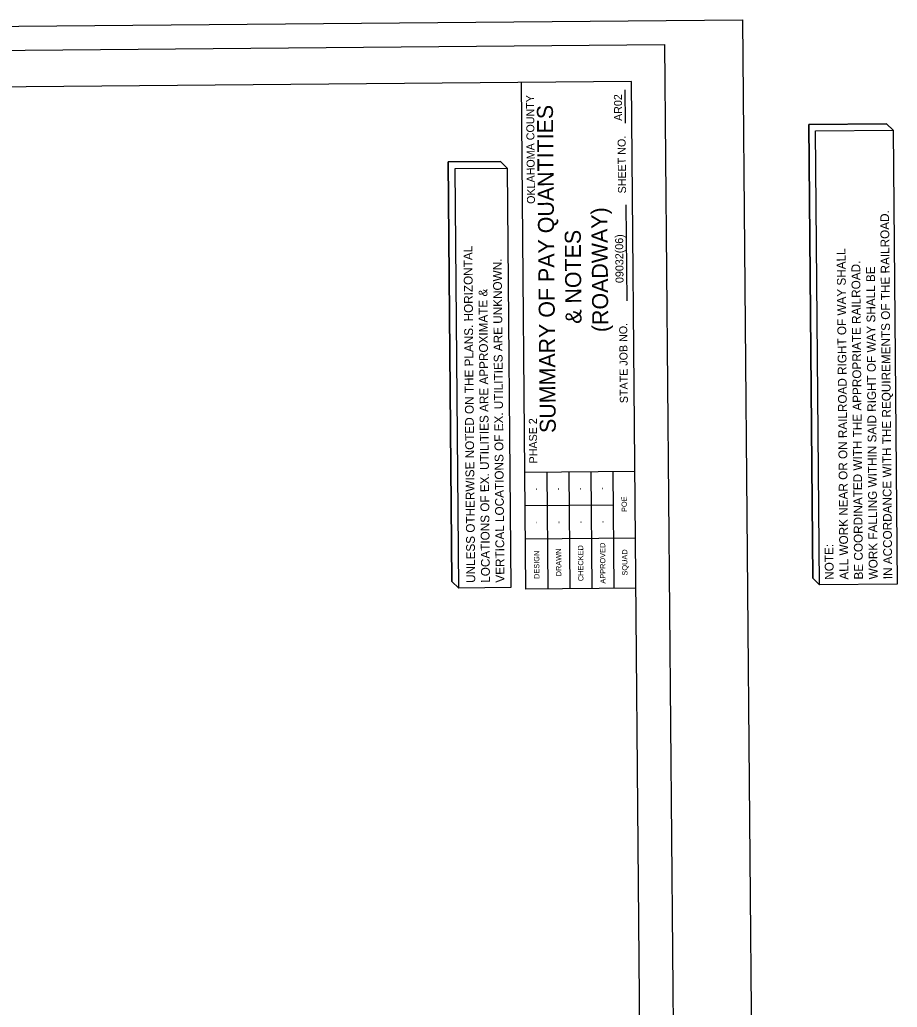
# Model space of a CAD drawing. Extents: x 2151899 to 2151927, y 142567 to 142686.
# Drawn here: x 2151913.59 to 2151926.74, y 142628.6 to 142643.41 of the extents above; entities that cross this region are included whole.
import ezdxf

# ---------------------------------------------------------------- set-up
doc = ezdxf.new("R2010")
doc.units = 0
for name, color, linetype in [('PR_RW_Txt', 7, 'Continuous'), ('PR_Shading_1', 7, 'Continuous'), ('SHT_Plan_Profile_Sheet_Txt', 7, 'Continuous'), ('SHT_Plot_Shape_Full', 7, 'Continuous'), ('SHT_Plot_Shape_Half', 7, 'Continuous'), ('SHT_Sheet_Border', 7, 'Continuous'), ('SHT_Standard_Sheet_Lines', 7, 'Continuous'), ('SHT_Standard_Sheet_Txt', 7, 'Continuous')]:
    doc.layers.add(name, color=color, linetype=linetype)

msp = doc.modelspace()

# ---------------------------------------------------------------- linework, layer by layer
at = {"layer": 'PR_Shading_1'}
for p, q in [((2151926.685, 142641.749), (2151926.584, 142641.848)), ((2151920.897, 142641.182), (2151920.796, 142641.281))]:
    msp.add_line(p, q, dxfattribs=at)
for points in [[(2151926.584, 142641.848), (2151925.419, 142641.838), (2151925.478, 142635.029), (2151925.579, 142634.93)], [(2151925.579, 142634.93), (2151925.52, 142641.739), (2151926.685, 142641.749)], [(2151920.796, 142641.281), (2151920.012, 142641.274), (2151920.067, 142634.982), (2151920.168, 142634.883)], [(2151920.168, 142634.883), (2151920.113, 142641.175), (2151920.897, 142641.182)]]:
    msp.add_lwpolyline(points, dxfattribs=at)
at = {"layer": 'SHT_Plan_Profile_Sheet_Txt'}
for points in [[(2151925.579, 142634.93), (2151925.478, 142635.029), (2151925.419, 142641.838), (2151926.584, 142641.848), (2151926.685, 142641.749)], [(2151920.168, 142634.883), (2151920.067, 142634.982), (2151920.012, 142641.274), (2151920.796, 142641.281), (2151920.897, 142641.182)]]:
    msp.add_lwpolyline(points, dxfattribs=at)
for points in [[(2151925.579, 142634.93), (2151925.52, 142641.739), (2151926.685, 142641.749), (2151926.744, 142634.94)], [(2151920.168, 142634.883), (2151920.113, 142641.175), (2151920.897, 142641.182), (2151920.952, 142634.889)]]:
    msp.add_lwpolyline(points, close=True, dxfattribs=at)
at = {"layer": 'SHT_Plot_Shape_Full'}
msp.add_lwpolyline([(2151900.742, 142607.199), (2151900.427, 142643.197), (2151924.426, 142643.407), (2151924.741, 142607.409)], close=True, dxfattribs=at)
at = {"layer": 'SHT_Plot_Shape_Half'}
msp.add_lwpolyline([(2151901.553, 142608.843), (2151901.255, 142642.842), (2151923.254, 142643.035), (2151923.552, 142609.036)], close=True, dxfattribs=at)
at = {"layer": 'SHT_Sheet_Border'}
for p, q in [((2151921.176, 142634.866), (2151921.109, 142642.466)), ((2151922.81, 142636.63), (2151921.16, 142636.616)), ((2151922.826, 142634.881), (2151921.176, 142634.866))]:
    msp.add_line(p, q, dxfattribs=at)
msp.add_lwpolyline([(2151923.035, 142610.981), (2151922.759, 142642.48), (2151901.76, 142642.296), (2151902.036, 142610.798)], close=True, dxfattribs=at)
at = {"layer": 'SHT_Standard_Sheet_Lines'}
for p, q in [((2151922.668, 142641.855), (2151922.664, 142642.357)), ((2151922.692, 142639.19), (2151922.679, 142640.63)), ((2151922.485, 142636.128), (2151921.164, 142636.116)), ((2151922.819, 142635.63), (2151921.168, 142635.616))]:
    msp.add_line(p, q, dxfattribs=at)
for points in [[(2151921.49, 142636.619), (2151921.506, 142634.869)], [(2151921.82, 142636.622), (2151921.836, 142634.872)], [(2151922.15, 142636.625), (2151922.166, 142634.875)], [(2151922.48, 142636.628), (2151922.496, 142634.878)]]:
    msp.add_lwpolyline(points, dxfattribs=at)

# ---------------------------------------------------------------- texts
at = {"layer": 'PR_RW_Txt'}
for s, height, p in [('IN ACCORDANCE WITH THE REQUIREMENTS OF THE RAILROAD.', 0.13163, (2151926.669, 142635.016)), ('UNLESS OTHERWISE NOTED ON THE PLANS. HORIZONTAL', 0.13163, (2151920.416, 142634.961)), ('ALL WORK NEAR OR ON RAILROAD RIGHT OF WAY SHALL', 0.13163, (2151926.011, 142635.01)), ('VERTICAL LOCATIONS OF EX. UTILITIES ARE UNKNOWN.', 0.13163, (2151920.855, 142634.965)), ('BE COORDINATED WITH THE APPROPRIATE RAILROAD.', 0.13163, (2151926.23, 142635.012)), ('WORK FALLING WITHIN SAID RIGHT OF WAY SHALL BE', 0.13163, (2151926.45, 142635.014)), ('LOCATIONS OF EX. UTILITIES ARE APPROXIMATE &', 0.13163, (2151920.636, 142634.963)), ('NOTE:', 0.1316, (2151925.791, 142635.008))]:
    msp.add_text(s, height=height, rotation=90.5017, dxfattribs=at).set_placement(p)
at = {"layer": 'SHT_Standard_Sheet_Txt'}
for s, height, p in [('AR02', 0.12, (2151922.619, 142641.89)), ('OKLAHOMA COUNTY', 0.12, (2151921.312, 142640.646)), ('SUMMARY OF PAY QUANTITIES', 0.24, (2151921.624, 142637.21)), ('SHEET NO. ', 0.12, (2151922.678, 142640.803)), ('(ROADWAY)', 0.24, (2151922.412, 142638.723)), ('& NOTES', 0.24, (2151922.01, 142638.848)), ('09032(06)', 0.12, (2151922.64, 142639.459)), ('STATE JOB NO.', 0.12, (2151922.705, 142637.657)), ('PHASE 2', 0.12, (2151921.346, 142636.753)), ('-', 0.08, (2151921.367, 142636.348)), ('-', 0.08, (2151921.697, 142636.351)), ('-', 0.08, (2151922.027, 142636.354)), ('-', 0.08, (2151922.357, 142636.357)), ('POE', 0.08, (2151922.691, 142636.024)), ('-', 0.08, (2151921.371, 142635.848)), ('-', 0.08, (2151921.702, 142635.851)), ('-', 0.08, (2151922.032, 142635.854)), ('-', 0.08, (2151922.362, 142635.857)), ('CHECKED', 0.08, (2151922.039, 142634.987)), ('APPROVED', 0.08, (2151922.37, 142634.95)), ('DESIGN', 0.08, (2151921.379, 142635.02)), ('DRAWN', 0.08, (2151921.708, 142635.059)), ('SQUAD', 0.08, (2151922.699, 142635.071))]:
    msp.add_text(s, height=height, rotation=90.5015, dxfattribs=at).set_placement(p)

doc.saveas('drawing.dxf')
